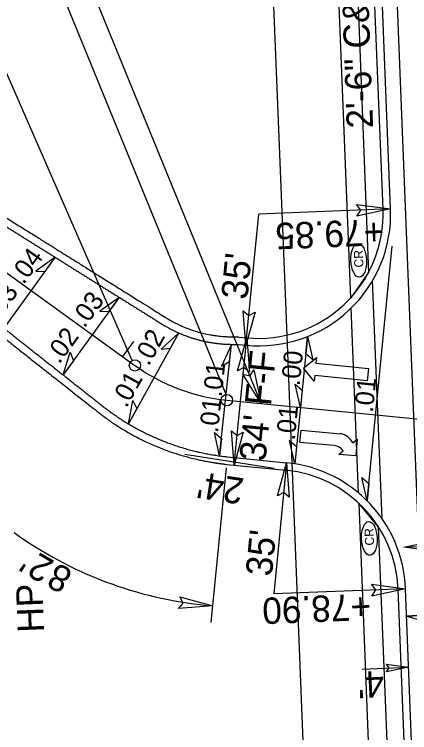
# Model space of a CAD drawing. Extents: x 1627861 to 1629601, y 761281 to 766239.
# Drawn here: x 1628260.9 to 1628365.8, y 764213 to 764403.8 of the extents above; entities that cross this region are included whole.
import ezdxf

# ---------------------------------------------------------------- set-up
doc = ezdxf.new("R2010")
doc.units = 0
for name, color, linetype in [('Exist Hydro Jurisdictional Stream or Body of Water', 7, 'Continuous'), ('Exist Other Culture Sign Leader', 7, 'Continuous'), ('Exist Property Tie Line Text', 7, 'Continuous'), ('Exist Right of Way Line Leader', 7, 'Continuous'), ('Exist Right of Way Monument Leader', 7, 'Continuous'), ('Exist Right of Way Monument Text', 7, 'Continuous'), ('Exist Utilities Gas Meter CELL', 7, 'Continuous'), ('Exist Utilities Gas Meter Cogo Elevation', 7, 'Continuous'), ('Exist Utilities Gas Meter Cogo Number', 7, 'Continuous'), ('Exist Utilities Gas UG Line', 7, 'Continuous'), ('Exist Utilities Power UG Cable SUE LOS B Cogo Point CELL', 7, 'Continuous'), ('Exist Utilities Telephone UG Cable SUE LOS B Cogo Comment', 7, 'Continuous'), ('Exist Utilities Water Fire Hydrant Cogo Elevation', 7, 'Continuous'), ('Exist Utilities Water Fire Hydrant Cogo Number', 7, 'Continuous'), ('Exist Utilities Water UG Line SUE LOS B Cogo Number', 7, 'Continuous'), ('Exist Utilities Water Valve CELL', 7, 'Continuous'), ('Scratch_Level_0', 7, 'Continuous'), ('Typical Terminator CELL', 7, 'Continuous')]:
    doc.layers.add(name, color=color, linetype=linetype)

msp = doc.modelspace()

# ---------------------------------------------------------------- linework, layer by layer
at = {"layer": 'Exist Hydro Jurisdictional Stream or Body of Water'}
msp.add_arc((1628322.14, 764351.07), 50, 234.1747, 264.4018, dxfattribs=at)
at = {"layer": 'Exist Property Tie Line Text'}
msp.add_line((1628289.65, 764312.86), (1628292.58, 764316.91), dxfattribs=at)
at = {"layer": 'Exist Right of Way Line Leader'}
for p, q in [((1628317.11, 764302.8), (1628269.51, 764419.31)), ((1628292.11, 764311.82), (1628245.8, 764417.86)), ((1628326.41, 764300.41), (1628279.53, 764415.15))]:
    msp.add_line(p, q, dxfattribs=at)
for centre in [(1628292.87, 764310.53), (1628317.26, 764301.31)]:
    msp.add_circle(centre, 1.5, dxfattribs=at)
at = {"layer": 'Exist Right of Way Monument Leader'}
for p, q in [((1628337.61, 764309.76), (1628341.06, 764312.63)), ((1628341.06, 764312.63), (1628340.91, 764311.13)), ((1628340.43, 764306.36), (1628337.61, 764309.76)), ((1628340.91, 764311.13), (1628354.84, 764309.73)), ((1628340.58, 764307.85), (1628340.43, 764306.36)), ((1628354.51, 764306.44), (1628340.58, 764307.85)), ((1628354.84, 764309.73), (1628354.51, 764306.44)), ((1628336.66, 764290.09), (1628336.97, 764293.38)), ((1628336.97, 764293.38), (1628347.47, 764292.4)), ((1628350.71, 764289.99), (1628351.86, 764290.94)), ((1628351.86, 764290.94), (1628351.5, 764286.56)), ((1628345.77, 764289.25), (1628336.66, 764290.09)), ((1628347.01, 764286.92), (1628348.16, 764287.87)), ((1628351.5, 764286.56), (1628347.01, 764286.92))]:
    msp.add_line(p, q, dxfattribs=at)
for centre, radius, start, end in [((1628346.21, 764287.32), 5.25, 30.6972, 76.0089), ((1628345.48, 764286), 3.27, 35.0268, 84.685)]:
    msp.add_arc(centre, radius, start, end, dxfattribs=at)
at = {"layer": 'Exist Right of Way Monument Text'}
for p, q in [((1628360.72, 764352.1), (1628349.87, 764627.31)), ((1628320.37, 764316.08), (1628322.33, 764315.88)), ((1628317.44, 764286.22), (1628333.14, 764284.68)), ((1628367.3, 764185.25), (1628364.7, 764251.23))]:
    msp.add_line(p, q, dxfattribs=at)
for centre, start, end in [((1628325.75, 764350.72), 264.4018, 2.2582), ((1628329.73, 764249.85), 2.2582, 84.4018)]:
    msp.add_arc(centre, 35, start, end, dxfattribs=at)
for points in [[(1628254.71, 764349.88), (1628255.18, 764349.58), (1628255.65, 764349.29), (1628256.12, 764348.99), (1628256.59, 764348.7), (1628257.06, 764348.4), (1628257.53, 764348.11), (1628258.01, 764347.82), (1628258.48, 764347.52), (1628258.95, 764347.23), (1628259.42, 764346.93), (1628259.89, 764346.64), (1628260.36, 764346.34), (1628260.83, 764346.05), (1628261.3, 764345.75), (1628261.77, 764345.46), (1628262.24, 764345.16), (1628262.71, 764344.87), (1628263.18, 764344.58), (1628263.65, 764344.28), (1628264.12, 764343.99), (1628264.6, 764343.69), (1628265.07, 764343.4), (1628265.54, 764343.1), (1628266.01, 764342.81), (1628266.48, 764342.51), (1628266.95, 764342.22), (1628267.42, 764341.92), (1628267.89, 764341.63), (1628268.36, 764341.34), (1628268.83, 764341.04), (1628269.3, 764340.75), (1628269.77, 764340.45), (1628270.24, 764340.16), (1628270.71, 764339.86), (1628271.19, 764339.57), (1628271.66, 764339.27), (1628272.13, 764338.98), (1628272.6, 764338.68), (1628273.07, 764338.39), (1628273.54, 764338.1), (1628274.01, 764337.8), (1628274.48, 764337.51), (1628274.95, 764337.21), (1628275.42, 764336.92), (1628275.89, 764336.62), (1628276.36, 764336.33), (1628276.83, 764336.03), (1628277.3, 764335.74), (1628277.78, 764335.45), (1628278.25, 764335.15), (1628278.72, 764334.86), (1628279.19, 764334.56), (1628279.66, 764334.27), (1628280.13, 764333.97), (1628280.6, 764333.68), (1628281.07, 764333.38), (1628281.54, 764333.09), (1628282.01, 764332.79), (1628282.48, 764332.5), (1628282.95, 764332.21), (1628283.42, 764331.91), (1628283.9, 764331.62), (1628284.37, 764331.32), (1628284.84, 764331.03), (1628285.31, 764330.73), (1628285.78, 764330.44), (1628286.25, 764330.14), (1628286.72, 764329.85), (1628287.19, 764329.55), (1628287.66, 764329.26), (1628288.13, 764328.97), (1628288.6, 764328.67), (1628289.07, 764328.38), (1628289.54, 764328.08)], [(1628242.39, 764332.8), (1628242.82, 764332.46), (1628243.26, 764332.12), (1628243.69, 764331.77), (1628244.13, 764331.43), (1628244.56, 764331.09), (1628245, 764330.74), (1628245.43, 764330.4), (1628245.87, 764330.06), (1628246.3, 764329.71), (1628246.74, 764329.37), (1628247.17, 764329.03), (1628247.61, 764328.68), (1628248.05, 764328.34), (1628248.48, 764327.99), (1628248.92, 764327.65), (1628249.35, 764327.31), (1628249.79, 764326.96), (1628250.22, 764326.62), (1628250.66, 764326.28), (1628251.09, 764325.93), (1628251.53, 764325.59), (1628251.96, 764325.25), (1628252.4, 764324.9), (1628252.83, 764324.56), (1628253.27, 764324.22), (1628253.7, 764323.87), (1628254.14, 764323.53), (1628254.58, 764323.19), (1628255.01, 764322.84), (1628255.45, 764322.5), (1628255.88, 764322.16), (1628256.32, 764321.81), (1628256.75, 764321.47), (1628257.19, 764321.12), (1628257.62, 764320.78), (1628258.06, 764320.44), (1628258.49, 764320.09), (1628258.93, 764319.75), (1628259.36, 764319.41), (1628259.8, 764319.06), (1628260.24, 764318.72), (1628260.67, 764318.38), (1628261.11, 764318.03), (1628261.54, 764317.69), (1628261.98, 764317.35), (1628262.41, 764317), (1628262.85, 764316.66), (1628263.28, 764316.32), (1628263.72, 764315.97), (1628264.15, 764315.63), (1628264.59, 764315.28), (1628265.02, 764314.94), (1628265.46, 764314.6), (1628265.89, 764314.25), (1628266.33, 764313.91), (1628266.77, 764313.57), (1628267.2, 764313.22), (1628267.64, 764312.88), (1628268.07, 764312.54), (1628268.51, 764312.19), (1628268.94, 764311.85), (1628269.38, 764311.51), (1628269.81, 764311.16), (1628270.25, 764310.82), (1628270.68, 764310.48), (1628271.12, 764310.13), (1628271.55, 764309.79), (1628271.99, 764309.44), (1628272.43, 764309.1), (1628272.86, 764308.76), (1628273.3, 764308.41), (1628273.73, 764308.07), (1628274.17, 764307.73), (1628274.6, 764307.38)], [(1628289.54, 764328.08), (1628290.01, 764327.79), (1628290.49, 764327.49), (1628290.96, 764327.2), (1628291.43, 764326.9), (1628291.9, 764326.61), (1628292.37, 764326.32), (1628292.84, 764326.02), (1628293.31, 764325.73), (1628293.78, 764325.43), (1628294.25, 764325.14), (1628294.72, 764324.84), (1628295.19, 764324.55), (1628295.66, 764324.25), (1628296.13, 764323.96), (1628296.6, 764323.66), (1628297.08, 764323.37), (1628297.55, 764323.08), (1628298.02, 764322.78), (1628298.49, 764322.49), (1628298.96, 764322.19), (1628299.43, 764321.9), (1628299.9, 764321.6), (1628300.37, 764321.31), (1628300.77, 764321.06), (1628301.13, 764320.86), (1628301.48, 764320.66), (1628301.84, 764320.46), (1628302.2, 764320.27), (1628302.56, 764320.08), (1628302.93, 764319.9), (1628303.29, 764319.72), (1628303.66, 764319.54), (1628304.03, 764319.37), (1628304.4, 764319.21), (1628304.77, 764319.04), (1628305.14, 764318.89), (1628305.52, 764318.73), (1628305.89, 764318.58), (1628306.27, 764318.44), (1628306.65, 764318.3), (1628307.03, 764318.16), (1628307.41, 764318.03), (1628307.79, 764317.9), (1628308.17, 764317.78), (1628308.56, 764317.66), (1628308.94, 764317.55), (1628309.33, 764317.44), (1628309.71, 764317.33), (1628310.1, 764317.23), (1628310.49, 764317.13), (1628310.88, 764317.04), (1628311.27, 764316.95), (1628311.66, 764316.87), (1628312.05, 764316.79), (1628312.44, 764316.72), (1628312.83, 764316.65), (1628313.22, 764316.58), (1628313.61, 764316.52), (1628314, 764316.46), (1628314.39, 764316.41), (1628314.79, 764316.36), (1628315.18, 764316.32), (1628315.57, 764316.28), (1628315.96, 764316.25), (1628316.35, 764316.22), (1628316.75, 764316.19), (1628317.14, 764316.17), (1628317.53, 764316.15), (1628317.92, 764316.14), (1628318.31, 764316.13), (1628318.7, 764316.13), (1628319.26, 764316.11), (1628320.37, 764316.08)], [(1628274.6, 764307.38), (1628275.04, 764307.04), (1628275.47, 764306.7), (1628275.91, 764306.35), (1628276.34, 764306.01), (1628276.78, 764305.67), (1628277.21, 764305.32), (1628277.65, 764304.98), (1628278.08, 764304.64), (1628278.52, 764304.29), (1628278.96, 764303.95), (1628279.39, 764303.61), (1628279.83, 764303.26), (1628280.26, 764302.92), (1628280.7, 764302.57), (1628281.13, 764302.23), (1628281.57, 764301.89), (1628282, 764301.54), (1628282.44, 764301.2), (1628282.87, 764300.86), (1628283.31, 764300.51), (1628283.74, 764300.17), (1628284.18, 764299.83), (1628284.61, 764299.48), (1628285.12, 764299.09), (1628285.69, 764298.66), (1628286.26, 764298.24), (1628286.83, 764297.83), (1628287.41, 764297.42), (1628288, 764297.02), (1628288.59, 764296.62), (1628289.18, 764296.23), (1628289.78, 764295.85), (1628290.38, 764295.48), (1628290.98, 764295.11), (1628291.6, 764294.74), (1628292.21, 764294.39), (1628292.83, 764294.04), (1628293.45, 764293.7), (1628294.08, 764293.36), (1628294.71, 764293.03), (1628295.35, 764292.71), (1628295.98, 764292.39), (1628296.63, 764292.09), (1628297.27, 764291.79), (1628297.92, 764291.49), (1628298.58, 764291.21), (1628299.23, 764290.93), (1628299.89, 764290.65), (1628300.55, 764290.39), (1628301.22, 764290.13), (1628301.89, 764289.88), (1628302.56, 764289.64), (1628303.24, 764289.4), (1628303.91, 764289.17), (1628304.6, 764288.95), (1628305.28, 764288.74), (1628305.96, 764288.53), (1628306.65, 764288.33), (1628307.34, 764288.14), (1628308.04, 764287.96), (1628308.73, 764287.78), (1628309.43, 764287.62), (1628310.13, 764287.46), (1628310.83, 764287.3), (1628311.53, 764287.16), (1628312.24, 764287.02), (1628312.95, 764286.89), (1628313.65, 764286.77), (1628314.36, 764286.66), (1628315.08, 764286.55), (1628315.79, 764286.45), (1628316.34, 764286.38), (1628317.44, 764286.22)]]:
    msp.add_spline(points, degree=3, dxfattribs=at)
at = {"layer": 'Exist Utilities Gas Meter CELL'}
for p, q in [((1628242.96, 764346.57), (1628292.87, 764310.53)), ((1628317.26, 764301.31), (1628399.82, 764293.22))]:
    msp.add_line(p, q, dxfattribs=at)
msp.add_arc((1628322.14, 764351.07), 50, 234.1747, 264.4018, dxfattribs=at)
at = {"layer": 'Exist Utilities Gas Meter Cogo Elevation'}
for p, q in [((1628358.72, 764352.02), (1628347.87, 764627.23)), ((1628320.56, 764318.07), (1628322.53, 764317.88)), ((1628317.24, 764284.23), (1628332.94, 764282.69)), ((1628365.3, 764185.18), (1628362.7, 764251.15))]:
    msp.add_line(p, q, dxfattribs=at)
for centre, start, end in [((1628325.75, 764350.72), 264.4018, 2.2582), ((1628329.73, 764249.85), 2.2582, 84.4018)]:
    msp.add_arc(centre, 33, start, end, dxfattribs=at)
for points, degree in [([(1628255.77, 764351.57), (1628267.38, 764344.31), (1628278.99, 764337.04), (1628290.6, 764329.78)], 2), ([(1628241.15, 764331.23), (1628251.89, 764322.76), (1628262.62, 764314.29), (1628273.36, 764305.81)], 2), ([(1628290.6, 764329.78), (1628292.99, 764328.29), (1628296.56, 764326.05), (1628300.15, 764323.8), (1628301.37, 764323.04), (1628301.4, 764323.02), (1628301.42, 764323.01), (1628301.43, 764323.01), (1628301.43, 764323), (1628301.43, 764323), (1628301.43, 764323), (1628301.43, 764323), (1628301.47, 764322.98), (1628301.5, 764322.96), (1628301.6, 764322.9), (1628301.67, 764322.86), (1628301.75, 764322.81), (1628301.77, 764322.8), (1628301.79, 764322.79), (1628301.79, 764322.79), (1628301.79, 764322.79), (1628301.79, 764322.79), (1628301.79, 764322.78), (1628301.8, 764322.78), (1628301.81, 764322.77), (1628301.83, 764322.76), (1628301.87, 764322.74), (1628301.9, 764322.72), (1628301.97, 764322.68), (1628302.01, 764322.66), (1628302.06, 764322.63), (1628302.08, 764322.62), (1628302.1, 764322.61), (1628302.11, 764322.6), (1628302.12, 764322.6), (1628302.12, 764322.59), (1628302.14, 764322.59), (1628302.15, 764322.58), (1628302.23, 764322.53), (1628302.3, 764322.49), (1628302.39, 764322.44), (1628302.41, 764322.43), (1628302.43, 764322.42), (1628302.44, 764322.42), (1628302.45, 764322.41), (1628302.45, 764322.41), (1628302.45, 764322.41), (1628302.45, 764322.41), (1628302.46, 764322.4), (1628302.51, 764322.38), (1628302.7, 764322.27), (1628302.88, 764322.17), (1628303.62, 764321.78), (1628304.21, 764321.49), (1628305.42, 764320.94), (1628306.03, 764320.68), (1628307.27, 764320.2), (1628307.89, 764319.97), (1628309.78, 764319.36), (1628311.07, 764319.02), (1628313.02, 764318.64), (1628313.67, 764318.53), (1628314.99, 764318.35), (1628315.65, 764318.28), (1628316.64, 764318.2), (1628316.97, 764318.18), (1628317.47, 764318.16), (1628317.67, 764318.15), (1628317.89, 764318.14), (1628317.95, 764318.14), (1628317.96, 764318.14), (1628317.97, 764318.14), (1628317.97, 764318.14), (1628317.97, 764318.14), (1628317.98, 764318.14), (1628318, 764318.14), (1628318.02, 764318.14), (1628318.12, 764318.14), (1628318.21, 764318.14), (1628318.31, 764318.13), (1628318.32, 764318.13), (1628318.34, 764318.13), (1628318.35, 764318.13), (1628318.35, 764318.13), (1628318.35, 764318.13), (1628318.35, 764318.13), (1628318.35, 764318.13), (1628318.35, 764318.13), (1628318.35, 764318.13), (1628318.37, 764318.13), (1628318.39, 764318.13), (1628318.44, 764318.13), (1628318.48, 764318.13), (1628318.58, 764318.13), (1628318.63, 764318.13), (1628318.71, 764318.13), (1628318.73, 764318.13), (1628318.75, 764318.13), (1628318.76, 764318.13), (1628318.77, 764318.13), (1628318.77, 764318.13), (1628318.77, 764318.13), (1628318.77, 764318.13), (1628318.77, 764318.13), (1628318.78, 764318.13), (1628318.8, 764318.13), (1628318.83, 764318.13), (1628319.02, 764318.12), (1628319.2, 764318.12), (1628319.73, 764318.1), (1628320.08, 764318.09), (1628320.43, 764318.08)], 3), ([(1628273.36, 764305.81), (1628276.54, 764303.3), (1628279.82, 764300.72), (1628283.15, 764298.09), (1628283.31, 764297.97), (1628283.36, 764297.92), (1628283.37, 764297.92), (1628283.38, 764297.91), (1628283.38, 764297.91), (1628283.38, 764297.91), (1628283.38, 764297.91), (1628283.38, 764297.91), (1628283.4, 764297.9), (1628283.44, 764297.86), (1628283.48, 764297.83), (1628283.61, 764297.73), (1628283.72, 764297.65), (1628283.85, 764297.55), (1628283.87, 764297.53), (1628283.9, 764297.51), (1628283.9, 764297.51), (1628283.91, 764297.5), (1628283.91, 764297.5), (1628283.91, 764297.5), (1628283.92, 764297.49), (1628283.94, 764297.47), (1628284.01, 764297.42), (1628284.08, 764297.37), (1628284.24, 764297.25), (1628284.34, 764297.17), (1628284.47, 764297.07), (1628284.5, 764297.05), (1628284.55, 764297.01), (1628284.63, 764296.96), (1628284.71, 764296.9), (1628284.87, 764296.78), (1628284.97, 764296.7), (1628285.09, 764296.62), (1628285.1, 764296.61), (1628285.13, 764296.59), (1628285.17, 764296.56), (1628285.26, 764296.49), (1628285.34, 764296.44), (1628286.24, 764295.79), (1628287.1, 764295.2), (1628288.85, 764294.06), (1628289.74, 764293.51), (1628291.55, 764292.46), (1628292.46, 764291.95), (1628294.31, 764290.98), (1628295.25, 764290.52), (1628297.14, 764289.64), (1628298.1, 764289.22), (1628301, 764288.04), (1628302.97, 764287.34), (1628305.97, 764286.44), (1628306.98, 764286.16), (1628309, 764285.65), (1628310.02, 764285.42), (1628311.56, 764285.11), (1628312.07, 764285.02), (1628312.84, 764284.88), (1628313.23, 764284.81), (1628313.68, 764284.74), (1628313.9, 764284.71), (1628314.01, 764284.69), (1628314.05, 764284.68), (1628314.06, 764284.68), (1628314.07, 764284.68), (1628314.1, 764284.68), (1628314.11, 764284.67), (1628314.26, 764284.65), (1628314.38, 764284.63), (1628314.58, 764284.6), (1628314.65, 764284.59), (1628314.73, 764284.58), (1628314.75, 764284.58), (1628314.78, 764284.57), (1628314.8, 764284.57), (1628314.85, 764284.56), (1628314.88, 764284.56), (1628315.04, 764284.54), (1628315.17, 764284.52), (1628315.35, 764284.5), (1628315.41, 764284.49), (1628315.48, 764284.48), (1628315.48, 764284.48), (1628315.5, 764284.48), (1628315.51, 764284.47), (1628315.53, 764284.47), (1628315.58, 764284.46), (1628316.13, 764284.39), (1628316.66, 764284.31), (1628317.16, 764284.24)], 3)]:
    msp.add_open_spline(points, degree=degree, dxfattribs=at)
at = {"layer": 'Exist Utilities Gas Meter Cogo Number'}
for points in [[(1628351.67, 764353.29), (1628360.72, 764352.1), (1628351.74, 764350.14), (1628352.83, 764351.79)], [(1628324.75, 764324.69), (1628322.33, 764315.88), (1628321.62, 764325.05), (1628323.1, 764323.75)], [(1628320.11, 764309.07), (1628322.53, 764317.88), (1628323.24, 764308.71), (1628321.76, 764310.01)], [(1628324.44, 764309.33), (1628326.41, 764300.41), (1628321.51, 764308.19), (1628323.42, 764307.73)], [(1628321.63, 764292.84), (1628319.21, 764284.04), (1628318.5, 764293.2), (1628319.98, 764291.9)], [(1628330.72, 764275.88), (1628333.14, 764284.68), (1628333.85, 764275.52), (1628332.37, 764276.82)], [(1628370.14, 764261.48), (1628364.26, 764262.31), (1628370.11, 764263.53), (1628369.39, 764262.47)], [(1628355.64, 764252.42), (1628364.7, 764251.23), (1628355.72, 764249.27), (1628356.8, 764250.92)], [(1628304.76, 764249.08), (1628313.56, 764246.66), (1628304.4, 764245.95), (1628305.7, 764247.43)], [(1628359.63, 764231.18), (1628365.52, 764230.4), (1628359.68, 764229.13), (1628360.39, 764230.2)]]:
    msp.add_lwpolyline(points, close=True, dxfattribs=at)
at = {"layer": 'Exist Utilities Gas UG Line'}
msp.add_line((1628408.48, 763242.45), (1628347.37, 764792.06), dxfattribs=at)
at = {"layer": 'Exist Utilities Telephone UG Cable SUE LOS B Cogo Comment'}
for p, q in [((1628358.46, 764269.83), (1628355.97, 764333.06)), ((1628352.18, 764276.69), (1628350.25, 764325.73))]:
    msp.add_line(p, q, dxfattribs=at)
at = {"layer": 'Exist Utilities Water Fire Hydrant Cogo Elevation'}
for centre in [(1628352.27, 764338.43), (1628355.1, 764264.59)]:
    msp.add_ellipse(centre, major_axis=(-0.18, 4.48), ratio=0.462467, dxfattribs=at)
at = {"layer": 'Exist Utilities Water Fire Hydrant Cogo Number'}
for p, q in [((1628333.03, 764325.09), (1628320.13, 764646.7)), ((1628341.38, 764111.82), (1628333.03, 764325.09))]:
    msp.add_line(p, q, dxfattribs=at)
at = {"layer": 'Exist Utilities Water UG Line SUE LOS B Cogo Number'}
for p, q in [((1628354.48, 764274.59), (1628361.11, 764342.21)), ((1628271.7, 764339.25), (1628258.1, 764320.4)), ((1628288.69, 764328.61), (1628273.82, 764308)), ((1628304.51, 764319.16), (1628291.16, 764295)), ((1628338.66, 764318.19), (1628335.35, 764284.39)), ((1628315.35, 764286.51), (1628318.47, 764316.13)), ((1628364.98, 764243.99), (1628392.96, 764245.1))]:
    msp.add_line(p, q, dxfattribs=at)
at = {"layer": 'Exist Utilities Water Valve CELL'}
for p, q in [((1628350.14, 764328.49), (1628337.55, 764647.86)), ((1628342.77, 764642.27), (1628354.88, 764335.22)), ((1628354.88, 764335.22), (1628350.14, 764328.49)), ((1628352.29, 764273.92), (1628356.64, 764163.8)), ((1628357.55, 764267.59), (1628352.29, 764273.92)), ((1628361.4, 764169.79), (1628357.55, 764267.59))]:
    msp.add_line(p, q, dxfattribs=at)
at = {"layer": 'Scratch_Level_0'}
for p, q in [((1628360.72, 764352.1), (1628325.75, 764350.72)), ((1628322.33, 764315.88), (1628325.75, 764350.72)), ((1628319.21, 764284.04), (1628322.53, 764317.88)), ((1628329.87, 764283.17), (1628306.15, 764286.87)), ((1628313.13, 764242.3), (1628317.16, 764283.35)), ((1628333.14, 764284.68), (1628329.73, 764249.85)), ((1628364.26, 764262.31), (1628392.24, 764263.42)), ((1628364.7, 764251.23), (1628329.73, 764249.85)), ((1628311.92, 764246.82), (1628313.56, 764246.66)), ((1628353.21, 764229.91), (1628365.52, 764230.4))]:
    msp.add_line(p, q, dxfattribs=at)
msp.add_arc((1628322.14, 764351.07), 104.75, 234.1747, 264.4018, dxfattribs=at)
at = {"layer": 'Typical Terminator CELL'}
for points in [[(1628271.7, 764339.25), (1628266.57, 764335.55), (1628269, 764335.5)], [(1628288.69, 764328.61), (1628283.56, 764324.92), (1628285.99, 764324.86)], [(1628304.51, 764319.16), (1628299.86, 764314.87), (1628302.27, 764315.11)], [(1628338.66, 764318.19), (1628340.06, 764312.02), (1628338.21, 764313.58)], [(1628318.47, 764316.13), (1628315.85, 764310.37), (1628317.98, 764311.53)], [(1628273.82, 764308), (1628275.71, 764314.04), (1628276.52, 764311.75)], [(1628336.82, 764299.39), (1628335.41, 764305.56), (1628337.27, 764304)], [(1628291.16, 764295), (1628292.31, 764301.22), (1628293.4, 764299.05)], [(1628315.35, 764286.51), (1628313.99, 764292.69), (1628315.84, 764291.11)], [(1628335.35, 764284.39), (1628333.94, 764290.56), (1628335.8, 764289)], [(1628354.48, 764274.59), (1628353.08, 764280.76), (1628354.93, 764279.19)], [(1628364.98, 764243.99), (1628371.06, 764242.23), (1628369.6, 764244.17)]]:
    msp.add_lwpolyline(points, close=True, dxfattribs=at)

# ---------------------------------------------------------------- texts
at = {"layer": 'Exist Other Culture Sign Leader'}
msp.add_text('HP', height=7, rotation=92.2582, dxfattribs=at).set_placement((1628268.76, 764239.72))
at = {"layer": 'Exist Utilities Power UG Cable SUE LOS B Cogo Point CELL'}
for s, rotation, p in [('+79.85', 182.2582, (1628358.9, 764349.47)), ("35'", 84.4018, (1628322.7, 764327.84)), ("34' F-F", 84.4018, (1628327.52, 764284.88)), ("24'", 171.1192, (1628322.12, 764280.47)), ("35'", 84.4018, (1628329.2, 764254.35)), ('2', 149.9549, (1628271.81, 764258.45)), ("'", 146.9268, (1628267.01, 764261.23)), ('8', 152.9831, (1628276.74, 764255.94)), ('+78.90', 182.2582, (1628355.4, 764249.95)), ("4'", 182.7862, (1628358.82, 764229.46))]:
    msp.add_text(s, height=7, rotation=rotation, dxfattribs=at).set_placement(p)
at = {"layer": 'Exist Utilities Water Fire Hydrant Cogo Elevation'}
for p in [(1628353.53, 764336.59), (1628356.36, 764262.75)]:
    msp.add_text('CR', height=2.4, rotation=92.2582, dxfattribs=at).set_placement(p)
at = {"layer": 'Exist Utilities Water UG Line SUE LOS B Cogo Number'}
for s, rotation, p in [('.04', 54.1747, (1628263.33, 764331.82)), ('.03', 54.1747, (1628256.67, 764322.49)), ('.03', 54.1747, (1628279.48, 764320.25)), ('.02', 54.1747, (1628272.79, 764310.71)), ('.02', 61.084, (1628296.53, 764310.16)), ('.00', 84.4018, (1628336.61, 764304.96)), ('.01', 84.0023, (1628315.9, 764302)), ('.01', 61.084, (1628290.61, 764299.04)), ('.01', 84.4018, (1628356.03, 764297.88)), ('.01', 84.0023, (1628314.9, 764292.49)), ('.01', 84.4018, (1628335.3, 764290.51))]:
    msp.add_text(s, height=5, rotation=rotation, dxfattribs=at).set_placement(p)
at = {"layer": 'Scratch_Level_0'}
msp.add_text('2\'-6" C&G', height=7, rotation=92.0586, dxfattribs=at).set_placement((1628356.1, 764373.59))

doc.saveas('drawing.dxf')
